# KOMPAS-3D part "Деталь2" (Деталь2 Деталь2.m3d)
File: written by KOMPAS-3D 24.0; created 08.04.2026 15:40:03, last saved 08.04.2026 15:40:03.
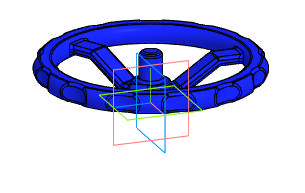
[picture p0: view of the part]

Document properties: Автор: R2D2; Полное имя файла: E:\Работа\Зайцев\VSO1121M-F-S Клапан запорный сальниковый DN.ru\DN15\исходные материалы\Деталь2 Деталь2.m3d

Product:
- Body: Твердое тело1  | qty 1
- Part/product: Деталь2
    additional columns: Типовые

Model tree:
1. Твердое тело1  (labels: Твердое тело1)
